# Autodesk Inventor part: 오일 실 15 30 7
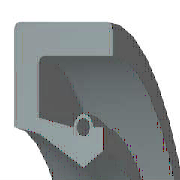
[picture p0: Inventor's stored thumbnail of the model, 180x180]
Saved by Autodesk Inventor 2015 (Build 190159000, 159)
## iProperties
IsCustomPart: 1
Created: 2012-02
Part Number: 오일 실 15 30 7
Material: 고무
Description: 오일-실
Document SubType Name: Modeling
Standard: KS B 2804
Designer: mduedu
Standards Organization: KS
Language: ko-KR
Size Designation: S - 15 30 7
Categories: <MemberInstance><Categories><Category DisplayName="샤프트 부품" InternalName="7f7aeb1f-a693-4053-b835-cee3144e0d98" Mnemonic="SHFT"><Category DisplayName="실링" Intern
Density: 0.93 g/cm^3
Appearance: 고무 - 검은색 - 버전 1.1
Author: mduedu
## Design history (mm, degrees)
revolve "본체" stored, may be unused: angle "d17" = 90 deg
revolve "스프링1" stored, may be unused: angle "d18" = 90 deg
body "Solid1"
sketch "스케치1"
  geometry: L1 (0, 15)-(7, 15); L2 (7, 15)-(7, 13.75); L3 (7, 13.75)-(1.75, 13.75); L4 (0, 15)-(0, 9.6); L5 (0, 9.6)-(1.75, 9.25); L6 (1.75, 9.25)-(4.9, 7.5); L7 (4.9, 7.5)-(0, 7.5); L8 (6.3, 8.375)-(6.3, 9.6); L9 (0, 0)-(9.586, 0) reference; L10 (4.9, 7.5)-(6.3, 8.375); L11 (0, 18)-(0, -3) reference; L12 (-1.917, 0)-(11.503, 0) reference; L13 (4.2, 9.6)-(1.75, 10.09); L14 (1.75, 10.09)-(1.75, 13.75); L15 (6.3, 9.6)-(5.6, 9.6); C1 r 0.455 at (4.9, 9.6); A1 r 0.7 centre (4.9, 9.6) between (5.6, 9.6) and (4.2, 9.6)
  constraints: 26 end point, 5 horizontal alignment, 4 perpendicular, 2 centre point, 2 collinear, 2 horizontal, 2 parallel, 2 point on circle, 2 point on line, 2 vertical alignment, 1 coincident
  dimensions: "d0" = 30 diameter of L1 L9 (= SD2); "d1" = 16.75 diameter of L8.start L9 (= ABDM); "d2" = 1.25 distance of L1.end L2.end (computed from SD); "d3" = 0.91 diameter of C1 (= SPDI); "d4" = 1.4 diameter of A1 (= SPDA); "d5" = 15 diameter of L6.end L9 (= NND); "d6" = 18.5 diameter of L5.end L9 (= TKDM); "d7" = 19.2 diameter of L4.end L9 (= HLDM); "d8" = 4.9 distance from line of C1.centre L4 (= SPDST); "d9" = 6.3 distance between parallel lines of L8 L4 (= SDI); "d10" = 7 distance between parallel lines of L2 L4 (= SWDT); "d12" = 1.75 distance between parallel lines of L14 L4 (= SD)
fillet "모깎기1" dims "d11" = 0.3 (= RR)
other parameters: "SD2" = 30 [user parameter; used in 1 equation term], "SWDT" = 7 [user parameter; used in 1 equation term], "RR" = 0.3 [user parameter; used in 1 equation term], "SD" = 1.75 [user parameter; used in 2 equation terms], "NND" = 15 [user parameter; used in 1 equation term], "SPDA" = 1.4 [user parameter; used in 1 equation term], "SPDI" = 0.91 [user parameter; used in 1 equation term], "TKDM" = 18.5 [user parameter; used in 1 equation term], "HLDM" = 19.2 [user parameter; used in 1 equation term], "ABDM" = 16.75 [user parameter; used in 1 equation term], "SDI" = 6.3 [user parameter; used in 1 equation term], "SPDST" = 4.9 [user parameter; used in 1 equation term], "d13" = 0, "d14" = 0, "d15" = 0, "LAB" = 0.35 [user parameter]
